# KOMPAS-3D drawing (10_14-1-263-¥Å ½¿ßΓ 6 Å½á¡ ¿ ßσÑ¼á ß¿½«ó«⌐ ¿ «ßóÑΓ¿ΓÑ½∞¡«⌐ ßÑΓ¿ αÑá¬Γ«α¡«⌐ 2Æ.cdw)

Views: Вид 1, Вид 2, Вид 3
Referenced files in C:\Program Files\ASCON\KOMPAS-3D V10\Sys\: Graphic.lcs
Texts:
  Стена
  Металлич. перекрытия
  Сэндвич-панели 100
  Блоки фундаментные 400
  Сэндвич-панели 150
  Текст на чертеже
  Размерные надписи
  Шероховатость
  Линия-выноска #1
  Линия-выноска #2
  Линия-выноска #3
  Отклонения формы и база
  Заголовок таблицы
  Ячейка таблицы
  Стрелка вида
  Обозначение изменения
  Фигурная скобка
  Номер узла
  Марка координационной оси
  VRCB
  Выносная надпись
  Обозначение узла
  Марка/позиционное обозначение с линией-выноской
  Марка/позиционное обозначение на линии
  Марка/позиционное обозначение без линии-выноски
  Normal
  txt
  Body Text
  heading 1
  Знак Знак Знак Знак Знак Знак
  Verdana
  Лит-Масса-Масштаб
  Материал-Предприятие
  MS Sans Serif
  Simplex
  Txt
  Title Specification
  Body Specification ( left align )
  Body Specificaton ( centered )
  Без имени
  Additional DXF text style 0
  Обычный
  Термин
  Список определений
  Адрес
  Цитаты
  Форматированный
  Courier New
  Z-конец формы
  Z-начало формы
  ТекстШаг1
  Денис
  heading 2
  AGOpus
  footer
  Title
  ООббыыччнныыйй
  Definition Term
  Definition List
  Address
  Blockquote
  Preformatted
  z-Bottom of Form
  z-Top of Form
  TXT
  header
  heading 8
  heading 3
  heading 6
  heading 7
  russ
  ТТееррммиинн
  ССппииссоокк ооппррееддееллеенниийй
  ААддрреесс
  ЦЦииттааттыы
  ФФооррммааттиирроовваанннныыйй
  Z-ккооннеецц ффооррммыы
  Z-ннааччааллоо ффооррммыы
  Абзац Знак
  heading 4
  heading 5
  heading 9
  GOST 2.304 type A
  rustxt
  цепи
  ссылки
  Маркировка
  Подпись в квадратике
  табл
  ЗОНА_привяз
  маркировка
  ГОСТ_МНЕ
  ESK - Обозначение
  текст переноса
  Тексты. 3,2
  Body Text 3
  клеммы, контакты
  тексты табл
  ISOCP
  HeliosLight
  Pa3
  Pa1
  Шрифт 2.5
  Заголовки
  RUSTXT
  NormalParagraphStyle
  Три с половиной
  style2
  Table Contents
  Table Heading
  Tahoma
  FR5
  надписи
  экспликация
  Здание
  Оси
  Примечания:
  Напряжение силовой и осветительной сети ~380/220 В.
  Нормируемая освещенность помещения принята согласно СНиП 23-05-95*.
  Заземление осветительной арматуры выполнить согласно ПУЭ.
  Принята коридорная схема управления освещением с использованием однополюсных
  переключателей (рис. 1) для возможности управления освещением с двух входов.
  Выключатели установить у дверей со стороны ручки. Высота установки выключателей - 1,5м,
  розеток - 0,8 м.
  При установке штепсельных розеток необходимо выдержать расстояние от заземлённых частей
  оборудования не менее 0,5 м.
  Прокладка кабелей сети рабочего освещения и розеточной сети 220 В предусматривается в
  ПВХ трубах по стенам. Уровни прокладки кабелей уточняются на месте  монтажа.
  Ввод кабелей осуществляется через технологическое отверстие  в полу здания.
  Предусмотреть естественное освещение здания реакторной.
  Вентиляторы В1, В2 установлены на крыше.
  Система управления пуском вентиляторов В1, В2 выполнена с помощью многофункциональных
  цифровых  термостатов и температурных сенсоров. Монтажную схему силового щита А2 см.лист 7.
  Схему обогрева шкафа см. лист 8.
  Предусмотреть естественную вентиляцию, представленную в виде 4-х вентиляционных
  решеток размером 1500х1000, привязку решеток см. лист 4
  Разводка кабелей и подключение всех устройств выполняется заводом изготовителем зданий
  реакторных.
  Шинки N и РЕ в шкафу А2 условно не показаны.
  Схема электроснабжения
  реакторной 2Т
  Поз.
  Кол.
  ед.,кг
  Приме-
  чание
  ГОСТ 50043.6-2000
  ГОСТ 51324.1-99
  ВКРм-6,3, исп.1
  ВКРм-12,5 исп.1
  LEDEL L-INDUSTRY NEW 12
  степень защиты IP65
  Розетка силовая, 2 модуля, DKC
  Переключатель серии Brava, DKC
  Вентилятор крышный, P=2,2 кВт
  Вентилятор крышный, P=4 кВт
  Светильник светодиодный
  Перечень основного оборудования
  План освещения и вентиляции
  Фаза
  Коридорная схема
  управления освещением
  Рис. 1
  (ЩСН 2 секция)
  QS1
  Acti 9
  iSW 4P
  QF1
  iC60N 2P
  хар-ка В
  QS2.2
  ВВГнг-LS 3х2,5
  ВВГнг-LS 5x6
  ВВГнг-LS 4x2,5
  ВВГнг-LS 4х2,5
  Освещение
  Розетка
  Вентилятор
  QF3
  iC60N 3P
  хар-ка С
  ВА 2129
  KM1
  iCT 4P
  KM2
  QF2
  QF4
  QF5
  QF6
  Cхема обогрева
  шкафа
  собственных нужд
  Cхема
  управления
  пуском
  вентиляторов
  POLYLINE_STYLE_0.73_RGB_0_0_0
  DIVIDE_RGB_0_0_0_SC_1_THICK_0.18
  DASHDOT1_RGB_0_0_0_SC_1_THICK_0.18
  осн 2
  K5LT_BASIC_RGB_0_0_255_THICK_0.3
  K5LT_AXLED_RGB_255_255_0_SC_1_THICK_0.09
  K5LT_REINFORCED_RGB_255_0_0_THICK_0.6
  POLYLINE_STYLE_0.30_RGB_0_0_255
  K5LT_THIN_RGB_0_0_0_THICK_0.09
  K5LT_THIN_INCLUDED_TO_HATCHING_RGB_0_0_0_THICK_0.09
  K5LT32769_RGB_0_0_0_THICK_0.09
  K5LT_THIN_RGB_0_0_0_THICK_0.13
  CONTINUOUS0
  Стили документа
  Бетон
  Бетон 0
  Бетон 1
  Бетон 2
  Бетон 3
  План и схема силовой
  и осветительной сети в
  Н.контр.
  Разраб.
  Скахин
  Андреева
  Реконструкция ПС 110 кВ Опорная
  (замена трансформаторов 16МВА на 40МВА)
  Ведомость эскизного проекта
Dimensions and other numbers on the sheet: 10/14-1-263-ЭП; 5; 0; 7; 2,5; 3.5; 2.5; 1,8; 2,5 (контакты, клеммы); 2.5 курсив; 2,5_3; 3,2 (надписи); 3,5_01; 2,5_01; 3,5_tabl; 5_заголовок; 2,3_; 3,2_; 3,2_зона не привяз; 2,5 грязносинь; 5,0_белый_подчёркнутый; 3,2; 3.2 фиол; 3,5; 3,2 элементы; 3,2 линия; 3,2 таблица; 3.2 маркировка; 2.5_Э5_надписи; 2.5_Э5_ссылки; 2.5_кабель; 3.2; 2.5 надписи; 3,2 (Зоны); 3 и 5; 2; 3; 4; 1; 115; 570; 4200; 4500; 4 кВт; 300; 2,2 кВт; 2АВ-8; 77; 11.12; 10/14-1-ИОС7.1-; 6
